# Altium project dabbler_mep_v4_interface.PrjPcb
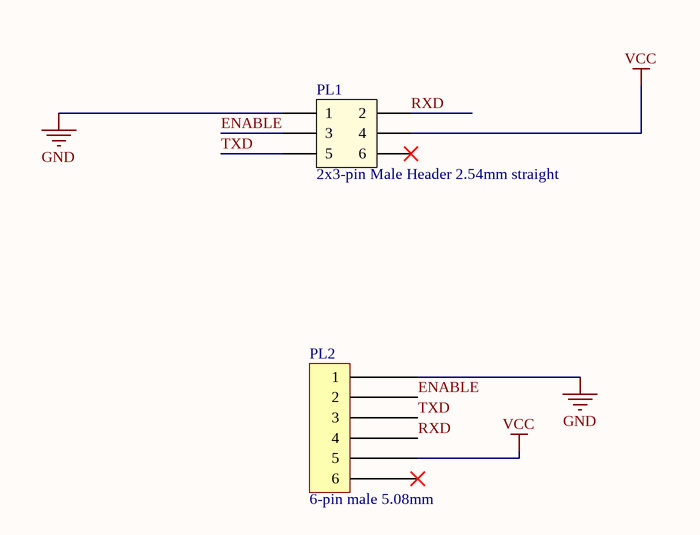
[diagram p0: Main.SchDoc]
GlobalProjectRevision: 1.0; GlobalProjectName: dabbler_mep_v4_interface.; GlobalDrawnBy: Mogens Groth Nicolaisen
1 sheet, 2 parts. Net scope: hierarchical (ports join the sheet entries above them; power ports are global).
Board file: dabbler_mep_v4_interface.PcbDoc

## Sheet Main.SchDoc: Main
size A3; DrawnBy: Mogens Groth Nicolaisen; DocumentNumber: 2; Revision: 1.0; SheetNumber: 2; SheetTotal: 7

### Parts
PL1  2x3-pin Male Header 2.54mm straight  [2x3-pin 2.54mm header]
PL2  6-pin male 5.08mm  [6-pin male 5.08mm-Footprint-1]

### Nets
GND: PL1.1 PL2.1
VCC: PL1.4 PL2.5
ENABLE: PL1.3 PL2.2
RXD: PL1.2 PL2.4
TXD: PL1.5 PL2.3

Not connected (* = marked no-connect by the designer): PL1 6*; PL2 6*

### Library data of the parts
PL1 = CMP-003-0019-0.0
PL2 = CMP-003-0039-0.0: KK® Header, Vertical, Round Pin, 6 Circuits, Tin (Sn) Plating, Pin Length 19.05mm; Contact Resistance: 10mR; Current Rating: 7A; Glow Wire Compliant: Non-compliant; Hole Diameter: 1.57mm; Insulation Resistance: 500GR; Number of Circuits: 6; Voltage Rating: 250V

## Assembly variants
Default: not fitted J1 PL2 PL2 PL3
